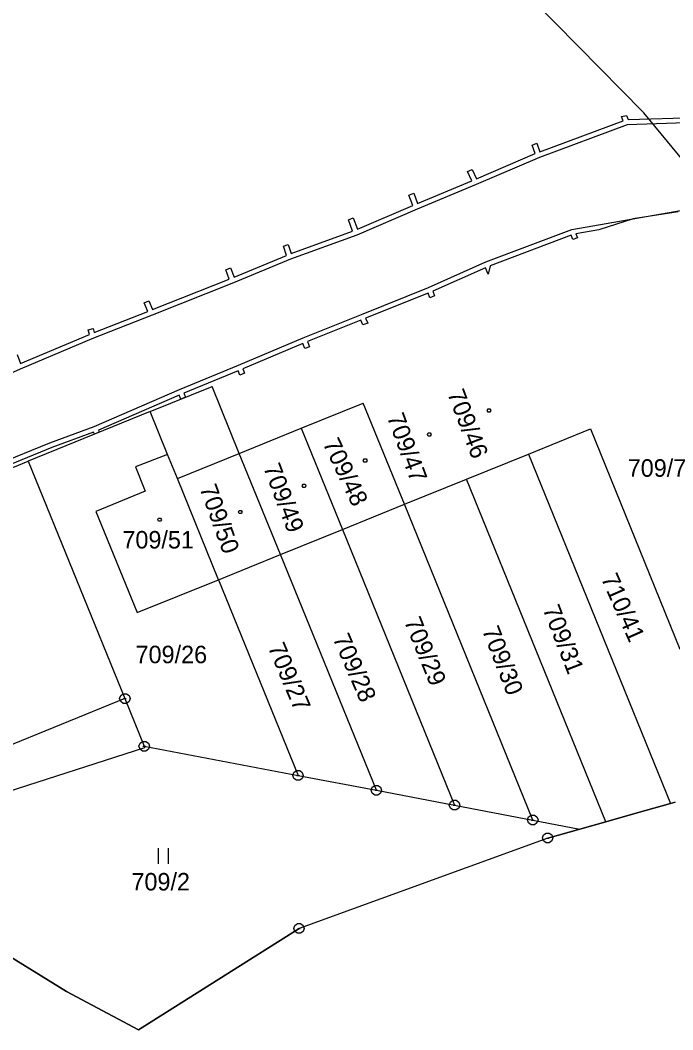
# Model space of a CAD drawing. Extents: x -759699 to -757730, y -1172308 to -1170857.
# Drawn here: x -757966.9 to -757903.5, y -1171062.2 to -1170964.1 of the extents above; entities that cross this region are included whole.
import ezdxf

# ---------------------------------------------------------------- set-up
doc = ezdxf.new("R2010")
doc.units = 0
for name, color, linetype in [('Vrstva 1', 7, 'Continuous'), ('Vrstva 11', 7, 'Continuous'), ('Vrstva 12', 7, 'Continuous'), ('Vrstva 13', 7, 'Continuous'), ('Vrstva 2', 7, 'Continuous'), ('Vrstva 3', 7, 'Continuous'), ('Vrstva 4', 7, 'Continuous'), ('Vrstva 5', 7, 'Continuous'), ('Vrstva 8', 7, 'Continuous')]:
    doc.layers.add(name, color=color, linetype=linetype)

msp = doc.modelspace()

# ---------------------------------------------------------------- linework, layer by layer
at = {"layer": 'Vrstva 1'}
for p, q in [((-757954.26, -1171002.09), (-757948.24, -1170999.65)), ((-757948.24, -1170999.65), (-757948.24, -1170999.65)), ((-757945.59, -1171006.16), (-757948.24, -1170999.65)), ((-757954.26, -1171002.09), (-757966.1, -1171006.91)), ((-757952.56, -1171006.26), (-757954.26, -1171002.09)), ((-757929.54, -1171011.1), (-757933.54, -1171001.27)), ((-757933.54, -1171001.27), (-757933.54, -1171001.27)), ((-757939.57, -1171003.72), (-757939.57, -1171003.72)), ((-757939.57, -1171003.72), (-757935.57, -1171013.55)), ((-757917.5, -1171006.22), (-757911.47, -1171003.78)), ((-757911.47, -1171003.78), (-757911.47, -1171003.78)), ((-757911.47, -1171003.78), (-757911.47, -1171003.78)), ((-757911.47, -1171003.78), (-757902.77, -1171025.17)), ((-757982.93, -1171013.75), (-757966.1, -1171006.91)), ((-757966.1, -1171006.91), (-757956.71, -1171029.99)), ((-757952.56, -1171006.26), (-757955.68, -1171007.48)), ((-757951.61, -1171008.61), (-757952.56, -1171006.26)), ((-757941.59, -1171015.99), (-757945.59, -1171006.16)), ((-757923.52, -1171008.66), (-757917.5, -1171006.22)), ((-757917.5, -1171006.22), (-757917.5, -1171006.22)), ((-757917.5, -1171006.22), (-757903.69, -1171040.18)), ((-757955.68, -1171007.48), (-757954.73, -1171009.84)), ((-757947.61, -1171018.43), (-757951.61, -1171008.61)), ((-757929.54, -1171011.1), (-757923.52, -1171008.66)), ((-757909.98, -1171041.95), (-757923.52, -1171008.66)), ((-757923.52, -1171008.66), (-757923.52, -1171008.66)), ((-757954.73, -1171009.84), (-757959.52, -1171011.79)), ((-757959.52, -1171011.79), (-757955.53, -1171021.63)), ((-757935.57, -1171013.55), (-757929.54, -1171011.1)), ((-757917.06, -1171041.79), (-757929.54, -1171011.1)), ((-757941.59, -1171015.99), (-757935.57, -1171013.55)), ((-757935.57, -1171013.55), (-757924.67, -1171040.34)), ((-757947.61, -1171018.43), (-757941.59, -1171015.99)), ((-757932.27, -1171038.9), (-757941.59, -1171015.99)), ((-757955.53, -1171021.63), (-757947.61, -1171018.43)), ((-757947.61, -1171018.43), (-757939.87, -1171037.46)), ((-757956.71, -1171029.99), (-758013.33, -1171052.94)), ((-757956.71, -1171029.99), (-757954.83, -1171034.62)), ((-757954.81, -1171034.78), (-757985.01, -1171044.46)), ((-757954.83, -1171034.62), (-757954.81, -1171034.78)), ((-757954.83, -1171034.62), (-757939.87, -1171037.46)), ((-757939.87, -1171037.46), (-757932.27, -1171038.9)), ((-757932.27, -1171038.9), (-757924.67, -1171040.34)), ((-757924.67, -1171040.34), (-757917.06, -1171041.79)), ((-757906.92, -1171041.09), (-757903.69, -1171040.18)), ((-757903.69, -1171040.18), (-757903.23, -1171040.05)), ((-757909.98, -1171041.95), (-757906.92, -1171041.09)), ((-757917.06, -1171041.79), (-757912.49, -1171042.66)), ((-757912.49, -1171042.66), (-757909.98, -1171041.95)), ((-757915.62, -1171043.54), (-757912.49, -1171042.66)), ((-757915.62, -1171043.54), (-757939.78, -1171052.33)), ((-757985.01, -1171044.46), (-757962.39, -1171058.46)), ((-757955.38, -1171062.17), (-757939.78, -1171052.33)), ((-757962.39, -1171058.46), (-757955.38, -1171062.17))]:
    msp.add_line(p, q, dxfattribs=at)
at = {"layer": 'Vrstva 11'}
for p, q in [((-757912.63, -1170966.62), (-757919.65, -1170959.5)), ((-757906.38, -1170972.96), (-757912.63, -1170966.62)), ((-757906.28, -1170973.07), (-757906.38, -1170972.96)), ((-757898.94, -1170982), (-757906.28, -1170973.07)), ((-757903.69, -1171040.18), (-757906.92, -1171041.09)), ((-757903.23, -1171040.05), (-757903.69, -1171040.18)), ((-757906.92, -1171041.09), (-757909.98, -1171041.95)), ((-757909.98, -1171041.95), (-757912.49, -1171042.66)), ((-757912.49, -1171042.66), (-757915.62, -1171043.54)), ((-757915.62, -1171043.54), (-757939.78, -1171052.33)), ((-757962.39, -1171058.46), (-757985.01, -1171044.46)), ((-757939.78, -1171052.33), (-757955.38, -1171062.17)), ((-757955.38, -1171062.17), (-757962.39, -1171058.46))]:
    msp.add_line(p, q, dxfattribs=at)
at = {"layer": 'Vrstva 12'}
for p, q in [((-757939.57, -1171003.72), (-757933.54, -1171001.27)), ((-757929.54, -1171011.1), (-757933.54, -1171001.27)), ((-757933.54, -1171001.27), (-757933.54, -1171001.27)), ((-757929.54, -1171011.1), (-757933.54, -1171001.27)), ((-757945.59, -1171006.16), (-757939.57, -1171003.72)), ((-757939.57, -1171003.72), (-757935.57, -1171013.55)), ((-757939.57, -1171003.72), (-757935.57, -1171013.55)), ((-757917.5, -1171006.22), (-757911.47, -1171003.78)), ((-757911.47, -1171003.78), (-757911.47, -1171003.78)), ((-757911.47, -1171003.78), (-757911.47, -1171003.78)), ((-757911.47, -1171003.78), (-757911.47, -1171003.78)), ((-757952.56, -1171006.26), (-757955.68, -1171007.48)), ((-757951.61, -1171008.61), (-757952.56, -1171006.26)), ((-757951.61, -1171008.61), (-757945.59, -1171006.16)), ((-757941.59, -1171015.99), (-757945.59, -1171006.16)), ((-757941.59, -1171015.99), (-757945.59, -1171006.16)), ((-757923.52, -1171008.66), (-757917.5, -1171006.22)), ((-757917.5, -1171006.22), (-757917.5, -1171006.22)), ((-757917.5, -1171006.22), (-757917.5, -1171006.22)), ((-757955.68, -1171007.48), (-757954.73, -1171009.84)), ((-757947.61, -1171018.43), (-757951.61, -1171008.61)), ((-757947.61, -1171018.43), (-757951.61, -1171008.61)), ((-757929.54, -1171011.1), (-757923.52, -1171008.66)), ((-757923.52, -1171008.66), (-757923.52, -1171008.66)), ((-757923.52, -1171008.66), (-757923.52, -1171008.66)), ((-757954.73, -1171009.84), (-757959.52, -1171011.79)), ((-757959.52, -1171011.79), (-757955.53, -1171021.63)), ((-757935.57, -1171013.55), (-757929.54, -1171011.1)), ((-757941.59, -1171015.99), (-757935.57, -1171013.55)), ((-757947.61, -1171018.43), (-757941.59, -1171015.99)), ((-757955.53, -1171021.63), (-757947.61, -1171018.43))]:
    msp.add_line(p, q, dxfattribs=at)
at = {"layer": 'Vrstva 13'}
for p, q in [((-757908.45, -1170973.43), (-757907.96, -1170973.32)), ((-757908.28, -1170973.83), (-757908.45, -1170973.43)), ((-757907.96, -1170973.32), (-757907.79, -1170973.72)), ((-757907.79, -1170973.72), (-757900.34, -1170973.5)), ((-757907.9, -1170974.22), (-757916.43, -1170977.4)), ((-757916.37, -1170976.85), (-757908.28, -1170973.83)), ((-757900.25, -1170973.99), (-757907.9, -1170974.22)), ((-757917.12, -1170976.2), (-757916.66, -1170976.01)), ((-757916.83, -1170977.03), (-757917.12, -1170976.2)), ((-757916.66, -1170976.01), (-757916.37, -1170976.85)), ((-757916.43, -1170977.4), (-757922.56, -1170980.02)), ((-757922.54, -1170979.47), (-757916.83, -1170977.03)), ((-757923.42, -1170978.76), (-757922.96, -1170978.57)), ((-757922.96, -1170978.57), (-757922.54, -1170979.47)), ((-757923, -1170979.66), (-757923.42, -1170978.76)), ((-757922.56, -1170980.02), (-757928.31, -1170982.44)), ((-757928.27, -1170981.88), (-757923, -1170979.66)), ((-757929.1, -1170981.07), (-757928.64, -1170980.88)), ((-757928.73, -1170982.07), (-757929.1, -1170981.07)), ((-757928.64, -1170980.88), (-757928.27, -1170981.88)), ((-757928.31, -1170982.44), (-757934.17, -1170984.94)), ((-757934.11, -1170984.38), (-757928.73, -1170982.07)), ((-757913.28, -1170984.39), (-757898.96, -1170981.9)), ((-757934.98, -1170983.46), (-757934.51, -1170983.27)), ((-757934.58, -1170984.56), (-757934.98, -1170983.46)), ((-757934.51, -1170983.27), (-757934.11, -1170984.38)), ((-757907.3, -1170983.37), (-757910.64, -1170984.43)), ((-757902.93, -1170982.7), (-757907.3, -1170983.37)), ((-757921.63, -1170987.56), (-757913.28, -1170984.39)), ((-757910.64, -1170984.43), (-757912.87, -1170984.82)), ((-757934.17, -1170984.94), (-757940.6, -1170987.3)), ((-757940.54, -1170986.75), (-757934.58, -1170984.56)), ((-757913.35, -1170984.95), (-757921.2, -1170987.93)), ((-757913.18, -1170985.39), (-757913.35, -1170984.95)), ((-757912.72, -1170985.2), (-757913.18, -1170985.39)), ((-757912.87, -1170984.82), (-757912.72, -1170985.2)), ((-757941.31, -1170986.03), (-757940.85, -1170985.85)), ((-757941, -1170986.93), (-757941.31, -1170986.03)), ((-757940.85, -1170985.85), (-757940.54, -1170986.75)), ((-757940.6, -1170987.3), (-757946.15, -1170989.59)), ((-757946.1, -1170989.03), (-757941, -1170986.93)), ((-757946.9, -1170988.31), (-757946.44, -1170988.12)), ((-757946.56, -1170989.22), (-757946.9, -1170988.31)), ((-757946.44, -1170988.12), (-757946.1, -1170989.03)), ((-757927.2, -1170990.03), (-757921.63, -1170987.56)), ((-757921.67, -1170988.12), (-757926.78, -1170990.39)), ((-757921.42, -1170988.74), (-757921.67, -1170988.12)), ((-757921.2, -1170987.93), (-757921.42, -1170988.74)), ((-757954.02, -1170992.19), (-757946.56, -1170989.22)), ((-757946.15, -1170989.59), (-757954.07, -1170992.74)), ((-757933.73, -1170992.66), (-757927.2, -1170990.03)), ((-757954.84, -1170991.54), (-757954.37, -1170991.35)), ((-757954.37, -1170991.35), (-757954.02, -1170992.19)), ((-757927.25, -1170990.59), (-757933.31, -1170993.03)), ((-757927.08, -1170991.04), (-757927.25, -1170990.59)), ((-757926.61, -1170990.85), (-757927.08, -1170991.04)), ((-757926.78, -1170990.39), (-757926.61, -1170990.85)), ((-757954.49, -1170992.37), (-757954.84, -1170991.54)), ((-757954.07, -1170992.74), (-757959.76, -1170994.97)), ((-757959.69, -1170994.41), (-757954.49, -1170992.37)), ((-757939.37, -1170994.92), (-757933.73, -1170992.66)), ((-757933.77, -1170993.21), (-757938.95, -1170995.29)), ((-757933.57, -1170993.68), (-757933.77, -1170993.21)), ((-757933.31, -1170993.03), (-757933.11, -1170993.5)), ((-757960.28, -1170994.16), (-757959.8, -1170994.02)), ((-757960.15, -1170994.6), (-757960.28, -1170994.16)), ((-757959.8, -1170994.02), (-757959.69, -1170994.41)), ((-757933.11, -1170993.5), (-757933.57, -1170993.68)), ((-757959.76, -1170994.97), (-757966.88, -1170997.99)), ((-757966.84, -1170997.43), (-757960.15, -1170994.6)), ((-757945.67, -1170997.58), (-757939.37, -1170994.92)), ((-757939.41, -1170995.48), (-757945.25, -1170997.94)), ((-757939.22, -1170995.98), (-757939.41, -1170995.48)), ((-757938.76, -1170995.79), (-757939.22, -1170995.98)), ((-757938.95, -1170995.29), (-757938.76, -1170995.79)), ((-757967.19, -1170996.55), (-757966.84, -1170997.43)), ((-757966.88, -1170997.99), (-757975.37, -1171001.62)), ((-757951.39, -1170999.94), (-757945.67, -1170997.58)), ((-757945.71, -1170998.14), (-757950.97, -1171000.31)), ((-757945.54, -1170998.55), (-757945.71, -1170998.14)), ((-757945.25, -1170997.94), (-757945.08, -1170998.36)), ((-757945.08, -1170998.36), (-757945.54, -1170998.55)), ((-757959.71, -1171003.54), (-757951.39, -1170999.94)), ((-757951.43, -1171000.5), (-757959.29, -1171003.9)), ((-757951.28, -1171000.88), (-757951.43, -1171000.5)), ((-757950.82, -1171000.69), (-757951.28, -1171000.88)), ((-757950.97, -1171000.31), (-757950.82, -1171000.69)), ((-757963.99, -1171005.12), (-757959.71, -1171003.54)), ((-757959.76, -1171004.09), (-757963.81, -1171005.58)), ((-757959.67, -1171004.29), (-757959.76, -1171004.09)), ((-757959.2, -1171004.1), (-757959.67, -1171004.29)), ((-757959.29, -1171003.9), (-757959.2, -1171004.1)), ((-757984.22, -1171013.38), (-757963.99, -1171005.12)), ((-757963.81, -1171005.58), (-757983.45, -1171013.6))]:
    msp.add_line(p, q, dxfattribs=at)
at = {"layer": 'Vrstva 3'}
for p, q in [((-757953.46, -1171044.53), (-757953.46, -1171046.03)), ((-757952.46, -1171046.03), (-757952.46, -1171044.53))]:
    msp.add_line(p, q, dxfattribs=at)
at = {"layer": 'Vrstva 4'}
for p, q in [((-757939.57, -1171003.72), (-757933.54, -1171001.27)), ((-757933.54, -1171001.27), (-757933.54, -1171001.27)), ((-757945.59, -1171006.16), (-757939.57, -1171003.72)), ((-757951.61, -1171008.61), (-757945.59, -1171006.16))]:
    msp.add_line(p, q, dxfattribs=at)
at = {"layer": 'Vrstva 5'}
for points in [[(-757921.24, -1171001.84), (-757921.15, -1171001.99), (-757921.24, -1171002.14), (-757921.42, -1171002.14), (-757921.51, -1171001.99), (-757921.42, -1171001.84)], [(-757927.04, -1171004.17), (-757926.95, -1171004.32), (-757927.04, -1171004.47), (-757927.22, -1171004.47), (-757927.31, -1171004.32), (-757927.22, -1171004.17)], [(-757933.27, -1171006.7), (-757933.18, -1171006.85), (-757933.27, -1171007), (-757933.45, -1171007), (-757933.54, -1171006.85), (-757933.45, -1171006.7)], [(-757939.2, -1171009.16), (-757939.11, -1171009.31), (-757939.2, -1171009.46), (-757939.38, -1171009.46), (-757939.47, -1171009.31), (-757939.38, -1171009.16)], [(-757945.41, -1171011.71), (-757945.32, -1171011.86), (-757945.41, -1171012.01), (-757945.59, -1171012.01), (-757945.68, -1171011.86), (-757945.59, -1171011.71)], [(-757953.25, -1171012.46), (-757953.16, -1171012.61), (-757953.25, -1171012.76), (-757953.43, -1171012.76), (-757953.52, -1171012.61), (-757953.43, -1171012.46)]]:
    msp.add_lwpolyline(points, close=True, dxfattribs=at)
at = {"layer": 'Vrstva 8'}
for p, q in [((-757956.83, -1171029.99), (-757956.59, -1171029.99)), ((-757954.95, -1171034.62), (-757954.71, -1171034.62)), ((-757939.99, -1171037.46), (-757939.75, -1171037.46)), ((-757932.39, -1171038.9), (-757932.15, -1171038.9)), ((-757924.79, -1171040.34), (-757924.55, -1171040.34)), ((-757917.18, -1171041.79), (-757916.94, -1171041.79)), ((-757915.74, -1171043.54), (-757915.5, -1171043.54)), ((-757939.9, -1171052.33), (-757939.66, -1171052.33))]:
    msp.add_line(p, q, dxfattribs=at)
for points in [[(-757956.56, -1171029.51), (-757956.31, -1171029.69), (-757956.21, -1171029.98), (-757956.31, -1171030.27), (-757956.56, -1171030.45), (-757956.87, -1171030.45), (-757957.12, -1171030.27), (-757957.22, -1171029.98), (-757957.12, -1171029.69), (-757956.87, -1171029.51)], [(-757954.68, -1171034.14), (-757954.43, -1171034.32), (-757954.33, -1171034.61), (-757954.43, -1171034.9), (-757954.68, -1171035.08), (-757954.99, -1171035.08), (-757955.24, -1171034.9), (-757955.34, -1171034.61), (-757955.24, -1171034.32), (-757954.99, -1171034.14)], [(-757939.72, -1171036.98), (-757939.47, -1171037.16), (-757939.37, -1171037.45), (-757939.47, -1171037.74), (-757939.72, -1171037.92), (-757940.03, -1171037.92), (-757940.28, -1171037.74), (-757940.38, -1171037.45), (-757940.28, -1171037.16), (-757940.03, -1171036.98)], [(-757932.12, -1171038.42), (-757931.87, -1171038.6), (-757931.77, -1171038.89), (-757931.87, -1171039.18), (-757932.12, -1171039.36), (-757932.43, -1171039.36), (-757932.68, -1171039.18), (-757932.78, -1171038.89), (-757932.68, -1171038.6), (-757932.43, -1171038.42)], [(-757924.52, -1171039.86), (-757924.27, -1171040.04), (-757924.17, -1171040.33), (-757924.27, -1171040.62), (-757924.52, -1171040.8), (-757924.83, -1171040.8), (-757925.08, -1171040.62), (-757925.18, -1171040.33), (-757925.08, -1171040.04), (-757924.83, -1171039.86)], [(-757916.91, -1171041.31), (-757916.66, -1171041.49), (-757916.56, -1171041.78), (-757916.66, -1171042.07), (-757916.91, -1171042.25), (-757917.22, -1171042.25), (-757917.47, -1171042.07), (-757917.57, -1171041.78), (-757917.47, -1171041.49), (-757917.22, -1171041.31)], [(-757915.47, -1171043.06), (-757915.22, -1171043.24), (-757915.12, -1171043.53), (-757915.22, -1171043.82), (-757915.47, -1171044), (-757915.78, -1171044), (-757916.03, -1171043.82), (-757916.13, -1171043.53), (-757916.03, -1171043.24), (-757915.78, -1171043.06)], [(-757939.63, -1171051.85), (-757939.38, -1171052.03), (-757939.28, -1171052.32), (-757939.38, -1171052.61), (-757939.63, -1171052.79), (-757939.94, -1171052.79), (-757940.19, -1171052.61), (-757940.29, -1171052.32), (-757940.19, -1171052.03), (-757939.94, -1171051.85)]]:
    msp.add_lwpolyline(points, close=True, dxfattribs=at)

# ---------------------------------------------------------------- texts
at = {"layer": 'Vrstva 2'}
for s, rotation, p in [('709/46', 290.83338, (-757925.406, -1171000.322)), ('709/47', 290.20312, (-757931.268, -1171002.613)), ('709/48', 295.30245, (-757937.519, -1171005.175)), ('709/49', 290.66149, (-757943.286, -1171007.512)), ('709/50', 289.80205, (-757949.48, -1171009.523)), ('710/41', 293.87005, (-757910.474, -1171018.287)), ('709/31', 291.17715, (-757916.134, -1171021.271)), ('709/29', 292.15118, (-757929.61, -1171022.47)), ('709/28', 293.46898, (-757936.545, -1171024.118)), ('709/30', 291.11986, (-757922.024, -1171023.331)), ('709/27', 292.72414, (-757942.848, -1171024.979))]:
    msp.add_text(s, height=1.7, rotation=rotation, dxfattribs=at).set_placement(p)
for s, p in [('709/7', (-757907.843, -1171008.43)), ('709/51', (-757956.953, -1171015.4)), ('709/26', (-757955.673, -1171026.55)), ('709/2', (-757956.073, -1171048.63))]:
    msp.add_text(s, height=1.7, dxfattribs=at).set_placement(p)

doc.saveas('drawing.dxf')
